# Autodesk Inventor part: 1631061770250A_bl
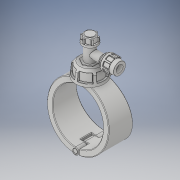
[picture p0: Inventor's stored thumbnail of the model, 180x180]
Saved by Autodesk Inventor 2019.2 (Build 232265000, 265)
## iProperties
Created: 2022-02
Part Number: 1631061770250A_bl
Material: Generic
Description: Plassadle Tapper 180x25
Document SubType Name: Modeling
Designer: comp2
Density: 1 g/cm^3
Appearance: Default
Author: comp2
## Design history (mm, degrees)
derived "16310.ipt"
feature "Solid1::16310.ipt" dims "ScaleForDerivedMember" = 10
feature "Solid2::16310.ipt" dims "ScaleForDerivedMember" = 10
feature "Solid3::16310.ipt" dims "ScaleForDerivedMember" = 10
feature "Solid4::16310.ipt" dims "ScaleForDerivedMember" = 10
tag "TaggingFeature1"
body "Solid1"
body "Solid2"
body "Solid3"
body "Solid4"
other parameters: "d7" = 209 [user parameter], "d8" = 85 deg [user parameter], "d9" = 45 deg [user parameter], "d10" = 102 [user parameter], "d11" = 49 [user parameter], "d12" = 34.3 [user parameter], "d13" = 35.7 [user parameter], "d14" = 55.08 [user parameter], "d15" = 2.45 [user parameter], "d16" = 2 [user parameter], "d17" = 2 [user parameter], "d18" = 29.4 [user parameter], "d19" = 7.35 [user parameter], "d20" = 1 [user parameter], "d21" = 30.6 [user parameter], "d22" = 1 [user parameter], "d23" = 14.7 [user parameter], "d24" = 106 [user parameter], "d27" = 144 [user parameter], "d29" = 54 [user parameter], "d31" = 43.2 [user parameter], "d32" = 42.4 [user parameter], "d33" = 14.84 [user parameter], "d34" = 93 deg [user parameter], "d35" = 2 [user parameter], "d36" = 4 [user parameter], "d39" = 45 deg [user parameter], "d40" = 4 [user parameter], "d41" = 5 [user parameter], "d42" = 4 [user parameter], "d46" = 51 [user parameter], "d47" = 27 [user parameter], "d48" = 49 [user parameter], "d49" = 4.4 [user parameter], "d51" = 0 [user parameter], "d52" = 28 [user parameter], "d53" = 121 [user parameter], "d54" = 38.5 [user parameter], "d55" = 0 [user parameter], "d56" = 22 [user parameter], "d57" = 22 [user parameter], "d59" = 0 [user parameter], "d61" = 0 [user parameter], "d62" = 38.5 [user parameter], "d63" = 0 [user parameter], "d65" = 0 [user parameter], "d67" = 0 [user parameter], "d69" = 0 [user parameter], "d70" = 1 [user parameter], "d71" = 105.6 [user parameter], "d72" = 0 [user parameter], "d73" = 2 [user parameter], "d77" = 25 [user parameter], "d78" = 86.7 [user parameter], "d79" = 5.1 [user parameter], "d80" = 60 deg [user parameter], "d81" = 5.1 [user parameter], "d84" = 0 [user parameter], "d85" = 1 [user parameter], "d87" = 360 deg [user parameter], "d90" = 0 [user parameter], "d91" = 1 [user parameter], "d93" = 60 deg [user parameter], "d94" = 3.06 [user parameter], "d95" = 3.06 [user parameter], "d97" = 0 [user parameter], "d98" = 0.5 [user parameter], "d100" = 360 deg [user parameter], "d102" = 2 [user parameter], "d105" = 0 [user parameter], "d106" = 45 deg [user parameter], "d107" = 2.7 [user parameter], "d108" = 2.7 [user parameter], "d109" = 2.95332 [user parameter], "d110" = -8 [user parameter], "d112" = 0 [user parameter], "d113" = 0.5 [user parameter], "d115" = 360 deg [user parameter], "d117" = 0.5 [user parameter], "d1" = 25 [user parameter], "E_" = 54 [user parameter], "E1" = 102 [user parameter], "H2" = 144 [user parameter], "H3" = 106 [user parameter], "H_costum" = 49 [user parameter]
